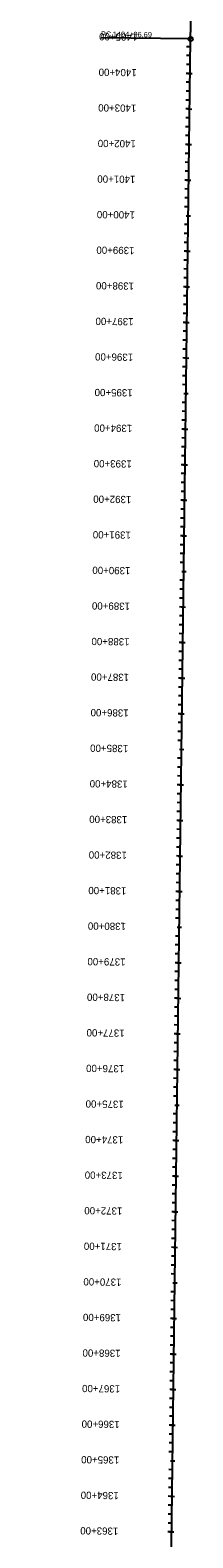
# Model space of a CAD drawing. Extents: x 20505176 to 20507193, y 7960287 to 7982631.
# Drawn here: x 20506258 to 20506714, y 7969085 to 7973323 of the extents above; entities that cross this region are included whole.
import ezdxf

# ---------------------------------------------------------------- set-up
doc = ezdxf.new("R2010")
doc.units = 0
for name, color, linetype in [('Alignment', 7, 'Continuous'), ('Default', 7, 'Continuous'), ('PC_REBAR GL 1', 7, 'Continuous'), ('TextAlignment', 7, 'Continuous'), ('TextAlignmentLrg', 7, 'Continuous'), ('TextAlignmentSml', 7, 'Continuous')]:
    doc.layers.add(name, color=color, linetype=linetype)

msp = doc.modelspace()

# ---------------------------------------------------------------- linework, layer by layer
at = {"layer": 'Alignment'}
msp.add_line((20506611.2, 7965595.6), (20506708.1, 7973298), dxfattribs=at)
msp.add_arc((20500978.6, 7973370.4), 5730, 359.27591, 22.87944, dxfattribs=at)
at = {"layer": 'Default'}
msp.add_line((20506611.2, 7965595.6), (20506708.1, 7973298), dxfattribs=at)
at = {"layer": 'PC_REBAR GL 1'}
msp.add_line((20506611.2, 7965595.6), (20506708.1, 7973298), dxfattribs=at)
at = {"layer": 'TextAlignment'}
for p in [(20506708.1, 7973298), (20506456.1, 7973301.1)]:
    msp.add_line(p, (20506456.1, 7973301.1), dxfattribs=at)
msp.add_circle((20506708.1, 7973298), 6.24, dxfattribs=at)
at = {"layer": 'TextAlignmentLrg'}
for p, q in [((20506702, 7973301.3), (20506714.3, 7973301.2)), ((20506706.9, 7973201.3), (20506696, 7973201.4)), ((20506705.6, 7973101.3), (20506694.7, 7973101.4)), ((20506704.4, 7973001.3), (20506693.5, 7973001.4)), ((20506703.1, 7972901.3), (20506692.2, 7972901.4)), ((20506695.7, 7972801.4), (20506708, 7972801.2)), ((20506700.6, 7972701.3), (20506689.7, 7972701.5)), ((20506699.3, 7972601.3), (20506688.4, 7972601.5)), ((20506698.1, 7972501.3), (20506687.2, 7972501.5)), ((20506696.8, 7972401.3), (20506685.9, 7972401.5)), ((20506689.4, 7972301.4), (20506701.7, 7972301.3)), ((20506694.3, 7972201.4), (20506683.4, 7972201.5)), ((20506693, 7972101.4), (20506682.1, 7972101.5)), ((20506691.8, 7972001.4), (20506680.9, 7972001.5)), ((20506690.5, 7971901.4), (20506679.6, 7971901.5)), ((20506683.2, 7971801.5), (20506695.4, 7971801.3)), ((20506688, 7971701.4), (20506677.1, 7971701.5)), ((20506686.8, 7971601.4), (20506675.8, 7971601.5)), ((20506685.5, 7971501.4), (20506674.6, 7971501.5)), ((20506684.2, 7971401.4), (20506673.3, 7971401.6)), ((20506676.9, 7971301.5), (20506689.1, 7971301.3)), ((20506681.7, 7971201.4), (20506670.8, 7971201.6)), ((20506680.5, 7971101.4), (20506669.5, 7971101.6)), ((20506679.2, 7971001.4), (20506668.3, 7971001.6)), ((20506677.9, 7970901.5), (20506667, 7970901.6)), ((20506670.6, 7970801.5), (20506682.8, 7970801.4)), ((20506675.4, 7970701.5), (20506664.5, 7970701.6)), ((20506674.2, 7970601.5), (20506663.3, 7970601.6)), ((20506672.9, 7970501.5), (20506662, 7970501.6)), ((20506671.7, 7970401.5), (20506660.7, 7970401.6)), ((20506664.3, 7970301.6), (20506676.5, 7970301.4)), ((20506669.1, 7970201.5), (20506658.2, 7970201.6)), ((20506667.9, 7970101.5), (20506657, 7970101.7)), ((20506666.6, 7970001.5), (20506655.7, 7970001.7)), ((20506665.4, 7969901.5), (20506654.4, 7969901.7)), ((20506658, 7969801.6), (20506670.2, 7969801.5)), ((20506662.9, 7969701.6), (20506651.9, 7969701.7)), ((20506661.6, 7969601.6), (20506650.7, 7969601.7)), ((20506660.3, 7969501.6), (20506649.4, 7969501.7)), ((20506659.1, 7969401.6), (20506648.2, 7969401.7)), ((20506651.7, 7969301.7), (20506663.9, 7969301.5)), ((20506656.6, 7969201.6), (20506645.6, 7969201.7)), ((20506655.3, 7969101.6), (20506644.4, 7969101.7))]:
    msp.add_line(p, q, dxfattribs=at)
at = {"layer": 'TextAlignmentSml'}
for p, q in [((20506702, 7973301.3), (20506714.3, 7973301.2)), ((20506707.5, 7973251.3), (20506696.6, 7973251.4)), ((20506707.8, 7973276.3), (20506696.9, 7973276.4)), ((20506707.2, 7973226.3), (20506696.3, 7973226.4)), ((20506700.8, 7973201.4), (20506713, 7973201.2)), ((20506706.3, 7973151.3), (20506695.3, 7973151.4)), ((20506706.6, 7973176.3), (20506695.7, 7973176.4)), ((20506705.9, 7973126.3), (20506695, 7973126.4)), ((20506705.3, 7973076.3), (20506694.4, 7973076.4)), ((20506699.5, 7973101.4), (20506711.8, 7973101.2)), ((20506704.7, 7973026.3), (20506693.8, 7973026.4)), ((20506705, 7973051.3), (20506694.1, 7973051.4)), ((20506698.3, 7973001.4), (20506710.5, 7973001.2)), ((20506703.7, 7972951.3), (20506692.8, 7972951.4)), ((20506704.1, 7972976.3), (20506693.1, 7972976.4)), ((20506703.4, 7972926.3), (20506692.5, 7972926.4)), ((20506697, 7972901.4), (20506709.2, 7972901.2)), ((20506702.8, 7972876.3), (20506691.9, 7972876.4)), ((20506702.2, 7972826.3), (20506691.3, 7972826.4)), ((20506702.5, 7972851.3), (20506691.6, 7972851.4)), ((20506701.5, 7972776.3), (20506690.6, 7972776.4)), ((20506695.7, 7972801.4), (20506708, 7972801.2)), ((20506700.9, 7972726.3), (20506690, 7972726.4)), ((20506701.2, 7972751.3), (20506690.3, 7972751.4)), ((20506694.5, 7972701.4), (20506706.7, 7972701.2)), ((20506700, 7972651.3), (20506689, 7972651.5)), ((20506700.3, 7972676.3), (20506689.4, 7972676.5)), ((20506699.7, 7972626.3), (20506688.7, 7972626.5)), ((20506693.2, 7972601.4), (20506705.5, 7972601.2)), ((20506699, 7972576.3), (20506688.1, 7972576.5)), ((20506698.4, 7972526.3), (20506687.5, 7972526.5)), ((20506698.7, 7972551.3), (20506687.8, 7972551.5)), ((20506697.8, 7972476.3), (20506686.8, 7972476.5)), ((20506692, 7972501.4), (20506704.2, 7972501.3)), ((20506697.5, 7972451.3), (20506686.5, 7972451.5)), ((20506697.1, 7972426.3), (20506686.2, 7972426.5)), ((20506690.7, 7972401.4), (20506702.9, 7972401.3)), ((20506696.2, 7972351.3), (20506685.3, 7972351.5)), ((20506696.5, 7972376.3), (20506685.6, 7972376.5)), ((20506695.9, 7972326.3), (20506685, 7972326.5)), ((20506695.3, 7972276.3), (20506684.3, 7972276.5)), ((20506689.4, 7972301.4), (20506701.7, 7972301.3)), ((20506694.6, 7972226.4), (20506683.7, 7972226.5)), ((20506694.9, 7972251.3), (20506684, 7972251.5)), ((20506694, 7972176.4), (20506683.1, 7972176.5)), ((20506688.2, 7972201.4), (20506700.4, 7972201.3)), ((20506693.7, 7972151.4), (20506682.8, 7972151.5)), ((20506693.4, 7972126.4), (20506682.4, 7972126.5)), ((20506686.9, 7972101.4), (20506699.2, 7972101.3)), ((20506692.4, 7972051.4), (20506681.5, 7972051.5)), ((20506692.7, 7972076.4), (20506681.8, 7972076.5)), ((20506692.1, 7972026.4), (20506681.2, 7972026.5)), ((20506691.5, 7971976.4), (20506680.6, 7971976.5)), ((20506685.7, 7972001.4), (20506697.9, 7972001.3)), ((20506690.8, 7971926.4), (20506679.9, 7971926.5)), ((20506691.2, 7971951.4), (20506680.2, 7971951.5)), ((20506684.4, 7971901.5), (20506696.7, 7971901.3)), ((20506689.9, 7971851.4), (20506679, 7971851.5)), ((20506690.2, 7971876.4), (20506679.3, 7971876.5)), ((20506689.6, 7971826.4), (20506678.7, 7971826.5)), ((20506683.2, 7971801.5), (20506695.4, 7971801.3)), ((20506689, 7971776.4), (20506678, 7971776.5)), ((20506688.3, 7971726.4), (20506677.4, 7971726.5)), ((20506688.6, 7971751.4), (20506677.7, 7971751.5)), ((20506687.7, 7971676.4), (20506676.8, 7971676.5)), ((20506681.9, 7971701.5), (20506694.1, 7971701.3)), ((20506687.1, 7971626.4), (20506676.2, 7971626.5)), ((20506687.4, 7971651.4), (20506676.5, 7971651.5)), ((20506680.6, 7971601.5), (20506692.9, 7971601.3)), ((20506686.1, 7971551.4), (20506675.2, 7971551.5)), ((20506686.4, 7971576.4), (20506675.5, 7971576.5)), ((20506685.8, 7971526.4), (20506674.9, 7971526.5)), ((20506679.4, 7971501.5), (20506691.6, 7971501.3)), ((20506685.2, 7971476.4), (20506674.3, 7971476.5)), ((20506684.6, 7971426.4), (20506673.6, 7971426.6)), ((20506684.9, 7971451.4), (20506674, 7971451.6)), ((20506683.9, 7971376.4), (20506673, 7971376.6)), ((20506678.1, 7971401.5), (20506690.4, 7971401.3)), ((20506683.6, 7971351.4), (20506672.7, 7971351.6)), ((20506683.3, 7971326.4), (20506672.4, 7971326.6)), ((20506676.9, 7971301.5), (20506689.1, 7971301.3)), ((20506682.4, 7971251.4), (20506671.4, 7971251.6)), ((20506682.7, 7971276.4), (20506671.7, 7971276.6)), ((20506682, 7971226.4), (20506671.1, 7971226.6)), ((20506675.6, 7971201.5), (20506687.8, 7971201.4)), ((20506681.4, 7971176.4), (20506670.5, 7971176.6)), ((20506680.8, 7971126.4), (20506669.9, 7971126.6)), ((20506681.1, 7971151.4), (20506670.2, 7971151.6)), ((20506680.2, 7971076.4), (20506669.2, 7971076.6)), ((20506674.3, 7971101.5), (20506686.6, 7971101.4)), ((20506679.8, 7971051.4), (20506668.9, 7971051.6)), ((20506679.5, 7971026.4), (20506668.6, 7971026.6)), ((20506673.1, 7971001.5), (20506685.3, 7971001.4)), ((20506678.6, 7970951.5), (20506667.7, 7970951.6)), ((20506678.9, 7970976.5), (20506668, 7970976.6)), ((20506678.3, 7970926.5), (20506667.3, 7970926.6)), ((20506677.6, 7970876.5), (20506666.7, 7970876.6)), ((20506671.8, 7970901.5), (20506684.1, 7970901.4)), ((20506677, 7970826.5), (20506666.1, 7970826.6)), ((20506677.3, 7970851.5), (20506666.4, 7970851.6)), ((20506670.6, 7970801.5), (20506682.8, 7970801.4)), ((20506676.1, 7970751.5), (20506665.1, 7970751.6)), ((20506676.4, 7970776.5), (20506665.5, 7970776.6)), ((20506675.7, 7970726.5), (20506664.8, 7970726.6)), ((20506669.3, 7970701.5), (20506681.6, 7970701.4)), ((20506674.8, 7970651.5), (20506663.9, 7970651.6)), ((20506675.1, 7970676.5), (20506664.2, 7970676.6)), ((20506674.5, 7970626.5), (20506663.6, 7970626.6)), ((20506673.9, 7970576.5), (20506662.9, 7970576.6)), ((20506668.1, 7970601.6), (20506680.3, 7970601.4)), ((20506673.2, 7970526.5), (20506662.3, 7970526.6)), ((20506673.5, 7970551.5), (20506662.6, 7970551.6)), ((20506666.8, 7970501.6), (20506679, 7970501.4)), ((20506672.3, 7970451.5), (20506661.4, 7970451.6)), ((20506672.6, 7970476.5), (20506661.7, 7970476.6)), ((20506672, 7970426.5), (20506661.1, 7970426.6)), ((20506665.5, 7970401.6), (20506677.8, 7970401.4)), ((20506671.3, 7970376.5), (20506660.4, 7970376.6)), ((20506670.7, 7970326.5), (20506659.8, 7970326.6)), ((20506671, 7970351.5), (20506660.1, 7970351.6)), ((20506670.1, 7970276.5), (20506659.2, 7970276.6)), ((20506664.3, 7970301.6), (20506676.5, 7970301.4)), ((20506669.5, 7970226.5), (20506658.5, 7970226.6)), ((20506669.8, 7970251.5), (20506658.9, 7970251.6)), ((20506663, 7970201.6), (20506675.3, 7970201.4)), ((20506668.5, 7970151.5), (20506657.6, 7970151.7)), ((20506668.8, 7970176.5), (20506657.9, 7970176.7)), ((20506668.2, 7970126.5), (20506657.3, 7970126.7)), ((20506661.8, 7970101.6), (20506674, 7970101.4)), ((20506667.6, 7970076.5), (20506656.6, 7970076.7)), ((20506666.9, 7970026.5), (20506656, 7970026.7)), ((20506667.3, 7970051.5), (20506656.3, 7970051.7)), ((20506666.3, 7969976.5), (20506655.4, 7969976.7)), ((20506660.5, 7970001.6), (20506672.7, 7970001.5)), ((20506666, 7969951.5), (20506655.1, 7969951.7)), ((20506665.7, 7969926.5), (20506654.8, 7969926.7)), ((20506659.2, 7969901.6), (20506671.5, 7969901.5)), ((20506664.7, 7969851.5), (20506653.8, 7969851.7)), ((20506665.1, 7969876.5), (20506654.1, 7969876.7)), ((20506664.4, 7969826.5), (20506653.5, 7969826.7)), ((20506663.8, 7969776.5), (20506652.9, 7969776.7)), ((20506658, 7969801.6), (20506670.2, 7969801.5)), ((20506663.2, 7969726.5), (20506652.2, 7969726.7)), ((20506663.5, 7969751.5), (20506652.6, 7969751.7)), ((20506662.5, 7969676.6), (20506651.6, 7969676.7)), ((20506656.7, 7969701.6), (20506669, 7969701.5)), ((20506662.2, 7969651.6), (20506651.3, 7969651.7)), ((20506661.9, 7969626.6), (20506651, 7969626.7)), ((20506655.5, 7969601.6), (20506667.7, 7969601.5)), ((20506661, 7969551.6), (20506650, 7969551.7)), ((20506661.3, 7969576.6), (20506650.4, 7969576.7)), ((20506660.6, 7969526.6), (20506649.7, 7969526.7)), ((20506660, 7969476.6), (20506649.1, 7969476.7)), ((20506654.2, 7969501.6), (20506666.5, 7969501.5)), ((20506659.4, 7969426.6), (20506648.5, 7969426.7)), ((20506659.7, 7969451.6), (20506648.8, 7969451.7)), ((20506653, 7969401.7), (20506665.2, 7969401.5)), ((20506658.4, 7969351.6), (20506647.5, 7969351.7)), ((20506658.8, 7969376.6), (20506647.8, 7969376.7)), ((20506658.1, 7969326.6), (20506647.2, 7969326.7)), ((20506651.7, 7969301.7), (20506663.9, 7969301.5)), ((20506657.2, 7969251.6), (20506646.3, 7969251.7)), ((20506657.5, 7969276.6), (20506646.6, 7969276.7)), ((20506656.9, 7969226.6), (20506646, 7969226.7)), ((20506656.2, 7969176.6), (20506645.3, 7969176.7)), ((20506650.4, 7969201.7), (20506662.7, 7969201.5)), ((20506655.6, 7969126.6), (20506644.7, 7969126.7)), ((20506655.9, 7969151.6), (20506645, 7969151.7)), ((20506649.2, 7969101.7), (20506661.4, 7969101.5))]:
    msp.add_line(p, q, dxfattribs=at)

# ---------------------------------------------------------------- texts
at = {"layer": 'TextAlignment'}
for s, p in [('PC', (20506456.2, 7973304.4)), ('1404+96.69', (20506489.5, 7973304))]:
    msp.add_text(s, height=15, rotation=359.2759, dxfattribs=at).set_placement(p)
at = {"layer": 'TextAlignmentLrg'}
for s, rotation, p in [('1405+00', 179.309, (20506558.3, 7973313.3)), ('1400+00', 179.2791, (20506552, 7972813.4)), ('1395+00', 179.2791, (20506545.7, 7972313.4)), ('1390+00', 179.2791, (20506539.4, 7971813.5)), ('1385+00', 179.2791, (20506533.1, 7971313.5)), ('1380+00', 179.2791, (20506526.8, 7970813.6)), ('1375+00', 179.2791, (20506520.5, 7970313.6)), ('1370+00', 179.2791, (20506514.2, 7969813.6)), ('1365+00', 179.2791, (20506508, 7969313.7))]:
    msp.add_text(s, height=20.4, rotation=rotation, dxfattribs=at).set_placement(p)
at = {"layer": 'TextAlignmentSml'}
for s, rotation, p in [('1405+00', 179.309, (20506558.3, 7973313.3)), ('1404+00', 179.2791, (20506557, 7973213.4)), ('1403+00', 179.2791, (20506555.8, 7973113.4)), ('1402+00', 179.2791, (20506554.5, 7973013.4)), ('1401+00', 179.2791, (20506553.3, 7972913.4)), ('1400+00', 179.2791, (20506552, 7972813.4)), ('1399+00', 179.2791, (20506550.7, 7972713.4)), ('1398+00', 179.2791, (20506549.5, 7972613.4)), ('1397+00', 179.2791, (20506548.2, 7972513.4)), ('1396+00', 179.2791, (20506547, 7972413.4)), ('1395+00', 179.2791, (20506545.7, 7972313.4)), ('1394+00', 179.2791, (20506544.4, 7972213.4)), ('1393+00', 179.2791, (20506543.2, 7972113.4)), ('1392+00', 179.2791, (20506541.9, 7972013.5)), ('1391+00', 179.2791, (20506540.7, 7971913.5)), ('1390+00', 179.2791, (20506539.4, 7971813.5)), ('1389+00', 179.2791, (20506538.2, 7971713.5)), ('1388+00', 179.2791, (20506536.9, 7971613.5)), ('1387+00', 179.2791, (20506535.6, 7971513.5)), ('1386+00', 179.2791, (20506534.4, 7971413.5)), ('1385+00', 179.2791, (20506533.1, 7971313.5)), ('1384+00', 179.2791, (20506531.9, 7971213.5)), ('1383+00', 179.2791, (20506530.6, 7971113.5)), ('1382+00', 179.2791, (20506529.3, 7971013.5)), ('1381+00', 179.2791, (20506528.1, 7970913.5)), ('1380+00', 179.2791, (20506526.8, 7970813.6)), ('1379+00', 179.2791, (20506525.6, 7970713.6)), ('1378+00', 179.2791, (20506524.3, 7970613.6)), ('1377+00', 179.2791, (20506523.1, 7970513.6)), ('1376+00', 179.2791, (20506521.8, 7970413.6)), ('1375+00', 179.2791, (20506520.5, 7970313.6)), ('1374+00', 179.2791, (20506519.3, 7970213.6)), ('1373+00', 179.2791, (20506518, 7970113.6)), ('1372+00', 179.2791, (20506516.8, 7970013.6)), ('1371+00', 179.2791, (20506515.5, 7969913.6)), ('1370+00', 179.2791, (20506514.2, 7969813.6)), ('1369+00', 179.2791, (20506513, 7969713.6)), ('1368+00', 179.2791, (20506511.7, 7969613.6)), ('1367+00', 179.2791, (20506510.5, 7969513.7)), ('1366+00', 179.2791, (20506509.2, 7969413.7)), ('1365+00', 179.2791, (20506508, 7969313.7)), ('1364+00', 179.2791, (20506506.7, 7969213.7)), ('1363+00', 179.2791, (20506505.4, 7969113.7))]:
    msp.add_text(s, height=20.4, rotation=rotation, dxfattribs=at).set_placement(p)

doc.saveas('drawing.dxf')
